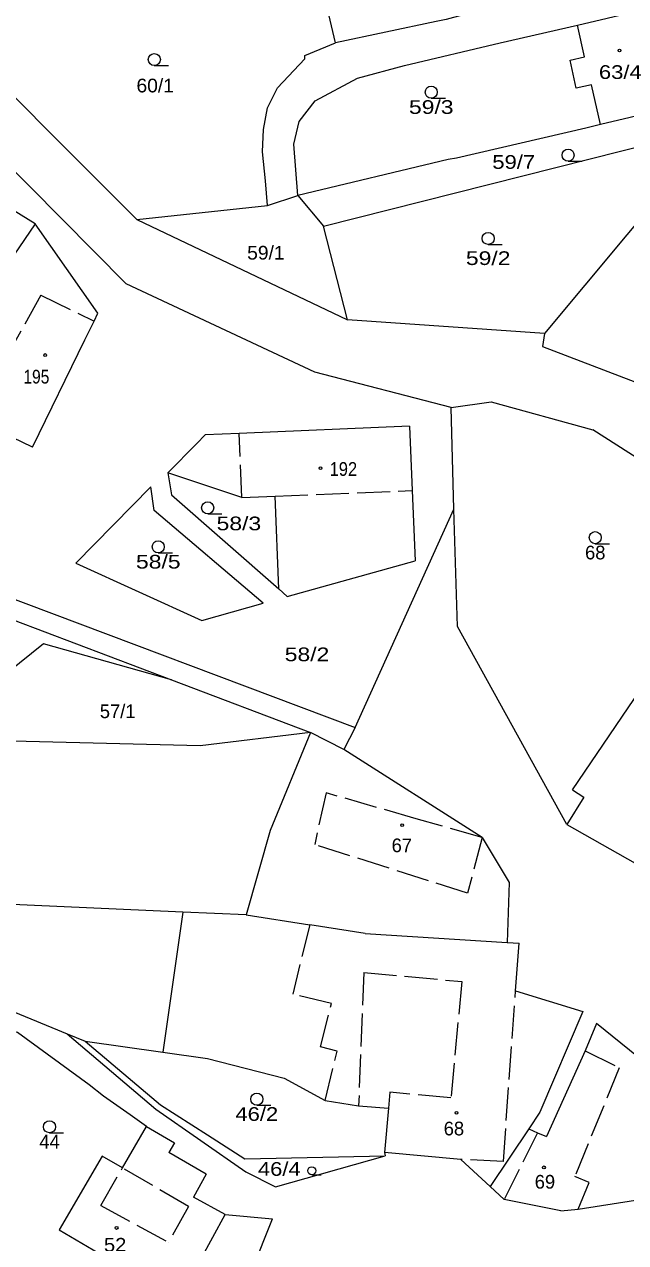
# Model space of a CAD drawing. Extents: x -590528 to -586543, y -1119609 to -1116685.
# Drawn here: x -589235.8 to -589161.2, y -1118589.8 to -1118438.6 of the extents above; entities that cross this region are included whole.
import ezdxf
from ezdxf.enums import TextEntityAlignment as Align

# ---------------------------------------------------------------- set-up
doc = ezdxf.new("R2010")
doc.units = 0
doc.header["$LTSCALE"] = 0.68
doc.linetypes.add('LONG_DASHED', pattern=[7.5, 6, -1.5])
for name, color, linetype, lineweight in [('1', 7, 'Continuous', 13), ('2', 7, 'LONG_DASHED', 13), ('3', 7, 'Continuous', 13), ('6', 7, 'Continuous', 13)]:
    doc.layers.add(name, color=color, linetype=linetype, lineweight=lineweight)

msp = doc.modelspace()

# ---------------------------------------------------------------- linework, layer by layer
at = {"layer": '1'}
for p, q in [((-589197.19, -1118440.86), (-589200.94, -1118424.78)), ((-589223.13, -1118470.78), (-589251.89, -1118441.81)), ((-589234.42, -1118463.35), (-589248.96, -1118454.42)), ((-589205.62, -1118461.09), (-589201.83, -1118459.82)), ((-589201.83, -1118459.82), (-589198.65, -1118463.65)), ((-589234.42, -1118463.35), (-589248.67, -1118484.2)), ((-589226.64, -1118474.44), (-589234.42, -1118463.35)), ((-589221.83, -1118462.82), (-589195.69, -1118475.28)), ((-589199.76, -1118481.77), (-589223.13, -1118470.78)), ((-589227.12, -1118475.43), (-589226.64, -1118474.44)), ((-589182.84, -1118486.15), (-589199.76, -1118481.77)), ((-589182.84, -1118486.15), (-589177.88, -1118485.44)), ((-589177.88, -1118485.44), (-589165.25, -1118488.91)), ((-589209.13, -1118489.36), (-589213.35, -1118489.54)), ((-589188, -1118488.46), (-589209.13, -1118489.36)), ((-589132.93, -1118509.71), (-589165.25, -1118488.91)), ((-589217.98, -1118494.24), (-589217.52, -1118497)), ((-589208.78, -1118497.33), (-589217.98, -1118494.24)), ((-589217.52, -1118497), (-589204.19, -1118508.66)), ((-589208.78, -1118497.33), (-589204.68, -1118497.16)), ((-589204.19, -1118508.66), (-589204.68, -1118497.16)), ((-589206.13, -1118510.45), (-589219.65, -1118498.92)), ((-589194.73, -1118525.89), (-589182.48, -1118498.78)), ((-589203.17, -1118509.62), (-589187.29, -1118505.17)), ((-589246.17, -1118506.49), (-589194.73, -1118525.89)), ((-589203.17, -1118509.62), (-589204.19, -1118508.66)), ((-589168.47, -1118537.9), (-589182.06, -1118513.33)), ((-589167.8, -1118533.6), (-589155.06, -1118514.8)), ((-589217.51, -1118519.97), (-589200.26, -1118526.5)), ((-589194.73, -1118525.89), (-589196.14, -1118528.59)), ((-589179, -1118539.52), (-589196.14, -1118528.59)), ((-589166.37, -1118534.51), (-589168.47, -1118537.9)), ((-589167.8, -1118533.6), (-589166.37, -1118534.51)), ((-589168.47, -1118537.9), (-589152.41, -1118547.01)), ((-589179, -1118539.52), (-589175.63, -1118545.12)), ((-589175.63, -1118545.12), (-589175.87, -1118552.54)), ((-589216.13, -1118548.79), (-589273.08, -1118546.25)), ((-589216.13, -1118548.79), (-589218.59, -1118566.18)), ((-589208.24, -1118549.12), (-589216.13, -1118548.79)), ((-589208.24, -1118549.12), (-589200.37, -1118550.35)), ((-589193.5, -1118551.43), (-589200.37, -1118550.35)), ((-589193.5, -1118551.43), (-589175.87, -1118552.54)), ((-589175.87, -1118552.54), (-589174.41, -1118552.63)), ((-589174.84, -1118558.56), (-589174.41, -1118552.63)), ((-589174.84, -1118558.56), (-589166.5, -1118561.12)), ((-589166.5, -1118561.12), (-589171.84, -1118573.64)), ((-589230.48, -1118563.88), (-589219.46, -1118573.25)), ((-589166.2, -1118566), (-589171.02, -1118576.66)), ((-589198.47, -1118572.17), (-589194.31, -1118572.85)), ((-589194.31, -1118572.85), (-589190.61, -1118573.11)), ((-589190.61, -1118573.11), (-589191.12, -1118578.61)), ((-589223.6, -1118580.55), (-589220.61, -1118575.41)), ((-589220.61, -1118575.41), (-589217.15, -1118577.42)), ((-589217.15, -1118577.42), (-589217.85, -1118578.62)), ((-589226.11, -1118579.09), (-589231.46, -1118588.24)), ((-589223.6, -1118580.55), (-589226.11, -1118579.09)), ((-589213.24, -1118581.3), (-589217.85, -1118578.62)), ((-589178, -1118582.85), (-589181.63, -1118579.49)), ((-589213.24, -1118581.3), (-589214.81, -1118584.18)), ((-589178, -1118582.85), (-589176.27, -1118584.45)), ((-589210.86, -1118586.33), (-589214.81, -1118584.18)), ((-589169.24, -1118585.88), (-589176.27, -1118584.45)), ((-589213.92, -1118591.95), (-589210.86, -1118586.33)), ((-589210.86, -1118586.33), (-589205, -1118586.86)), ((-589208.81, -1118596.45), (-589205, -1118586.86)), ((-589231.46, -1118588.24), (-589219.54, -1118595.2))]:
    msp.add_line(p, q, dxfattribs=at)
for points in [[(-589180.39, -1118419.11), (-589176.44, -1118428.18), (-589175.45, -1118430.45), (-589180.19, -1118432.28), (-589178.39, -1118436.62), (-589183.44, -1118437.97), (-589184.7, -1118438.23), (-589197.19, -1118440.86)], [(-589199.68, -1118448.07), (-589194.46, -1118445.28), (-589188.61, -1118443.7), (-589176.77, -1118440.88), (-589167.18, -1118438.67), (-589159.81, -1118436.94), (-589154.47, -1118435.78), (-589147.85, -1118434.23), (-589145.26, -1118446.55), (-589151.66, -1118448.03), (-589156.96, -1118449.29), (-589164.32, -1118451), (-589166.12, -1118451.49)], [(-589247.08, -1118437.51), (-589221.83, -1118462.82), (-589205.62, -1118461.09)], [(-589164.32, -1118451), (-589165.42, -1118446.1), (-589167.34, -1118446.51), (-589168.07, -1118443.03), (-589166.29, -1118442.63), (-589167.18, -1118438.67)], [(-589205.62, -1118461.09), (-589205.86, -1118458.03), (-589206.24, -1118454.4), (-589206.09, -1118451.65), (-589205.62, -1118448.94), (-589204.36, -1118446.46), (-589201, -1118442.87), (-589200.99, -1118442.47), (-589197.19, -1118440.86)], [(-589201.83, -1118459.82), (-589202.35, -1118453.47), (-589201.69, -1118450.65), (-589199.68, -1118448.07)], [(-589166.12, -1118451.49), (-589182.17, -1118455.21), (-589183.22, -1118455.38), (-589201.83, -1118459.82)], [(-589198.65, -1118463.65), (-589157.55, -1118453.25), (-589156.26, -1118452.88), (-589150.64, -1118451.54), (-589149.64, -1118453.61), (-589148.53, -1118453.2), (-589147.22, -1118453.38), (-589142.56, -1118452.06), (-589142.33, -1118452.99)], [(-589156.03, -1118458.71), (-589171.27, -1118476.97), (-589171.51, -1118478.56)], [(-589171.27, -1118476.97), (-589195.69, -1118475.28), (-589198.65, -1118463.65)], [(-589234.74, -1118491.09), (-589228.25, -1118477.75), (-589227.12, -1118475.43)], [(-589171.51, -1118478.56), (-589144.92, -1118488.74), (-589144.56, -1118485.98)], [(-589234.74, -1118491.09), (-589242.18, -1118487.51), (-589248.67, -1118484.2)], [(-589182.06, -1118513.33), (-589182.48, -1118498.78), (-589182.84, -1118486.15)], [(-589188, -1118488.46), (-589187.66, -1118496.44), (-589187.29, -1118505.17)], [(-589213.35, -1118489.54), (-589214.39, -1118490.6), (-589217.98, -1118494.24)], [(-589219.65, -1118498.92), (-589220.07, -1118496.01), (-589229.39, -1118505.45)], [(-589229.39, -1118505.45), (-589213.76, -1118512.59), (-589206.13, -1118510.45)], [(-589241.14, -1118511.02), (-589217.51, -1118519.97), (-589233.4, -1118515.49), (-589240.89, -1118521.5), (-589277.12, -1118521.87)], [(-589196.14, -1118528.59), (-589200.26, -1118526.5), (-589213.96, -1118528.14), (-589277.11, -1118526.56)], [(-589200.26, -1118526.5), (-589205.27, -1118538.65), (-589208.24, -1118549.12)], [(-589237.59, -1118560.95), (-589230.48, -1118563.88), (-589228.21, -1118564.82)], [(-589220.61, -1118575.41), (-589222.63, -1118573.97), (-589225.96, -1118571.65), (-589227.74, -1118570.24), (-589236.64, -1118563.74), (-589240.88, -1118562.79)], [(-589158.76, -1118567.49), (-589164.81, -1118562.6), (-589166.2, -1118566)], [(-589228.21, -1118564.82), (-589218.9, -1118572.7), (-589213.07, -1118576.42), (-589208.44, -1118579.4), (-589191.01, -1118579.06)], [(-589228.21, -1118564.82), (-589218.59, -1118566.18), (-589213.05, -1118566.97)], [(-589213.05, -1118566.97), (-589203.56, -1118569.39), (-589198.47, -1118572.17)], [(-589169.24, -1118585.88), (-589167.08, -1118585.66), (-589159.98, -1118584.55), (-589143.49, -1118576.26), (-589158.76, -1118567.49)], [(-589219.46, -1118573.25), (-589208.32, -1118581.04), (-589204.63, -1118582.88), (-589191.01, -1118579.06)], [(-589171.84, -1118573.64), (-589173.2, -1118575.68), (-589178, -1118582.85)], [(-589173.2, -1118575.68), (-589172.11, -1118576.17), (-589171.02, -1118576.66)], [(-589181.63, -1118579.49), (-589191.12, -1118578.61), (-589191.01, -1118579.06)]]:
    msp.add_lwpolyline(points, dxfattribs=at)
at = {"layer": '2'}
for p, q in [((-589233.74, -1118472.21), (-589242.18, -1118487.51)), ((-589233.74, -1118472.21), (-589227.12, -1118475.43)), ((-589208.78, -1118497.33), (-589209.13, -1118489.36)), ((-589204.68, -1118497.16), (-589187.66, -1118496.44)), ((-589200.37, -1118550.35), (-589202.49, -1118558.97)), ((-589193.68, -1118556.28), (-589194.31, -1118572.85)), ((-589193.68, -1118556.28), (-589181.52, -1118557.4)), ((-589176.36, -1118579.73), (-589174.84, -1118558.56)), ((-589197.69, -1118560.15), (-589202.49, -1118558.97)), ((-589199.02, -1118565.52), (-589197.69, -1118560.15)), ((-589196.96, -1118566.03), (-589199.02, -1118565.52)), ((-589198.47, -1118572.17), (-589196.96, -1118566.03)), ((-589166.2, -1118566), (-589161.98, -1118568.1)), ((-589161.98, -1118568.1), (-589167.49, -1118581.6)), ((-589172.11, -1118576.17), (-589176.27, -1118584.45)), ((-589176.36, -1118579.73), (-589181.63, -1118579.49)), ((-589226.3, -1118585.19), (-589223.6, -1118580.55)), ((-589215.43, -1118585.31), (-589223.6, -1118580.55)), ((-589165.72, -1118582.33), (-589167.49, -1118581.6)), ((-589167.08, -1118585.66), (-589165.72, -1118582.33)), ((-589226.3, -1118585.19), (-589217.87, -1118589.79)), ((-589215.43, -1118585.31), (-589217.87, -1118589.79))]:
    msp.add_line(p, q, dxfattribs=at)
for points in [[(-589179, -1118539.52), (-589187.17, -1118537.19), (-589198.35, -1118533.98), (-589199.76, -1118540.4)], [(-589179, -1118539.52), (-589180.8, -1118546.43), (-589199.76, -1118540.4)], [(-589181.52, -1118557.4), (-589182.86, -1118571.84), (-589190.43, -1118571.14), (-589190.61, -1118573.11)]]:
    msp.add_lwpolyline(points, dxfattribs=at)
at = {"layer": '6'}
for p, q in [((-589219.65, -1118443.71), (-589217.9, -1118443.71)), ((-589185.3, -1118447.75), (-589183.55, -1118447.75)), ((-589168.33, -1118455.57), (-589166.58, -1118455.57)), ((-589178.24, -1118465.91), (-589176.49, -1118465.91)), ((-589213.03, -1118499.35), (-589211.28, -1118499.35)), ((-589219.16, -1118504.19), (-589217.41, -1118504.19)), ((-589164.96, -1118503.05), (-589163.21, -1118503.05)), ((-589206.94, -1118572.75), (-589205.19, -1118572.75)), ((-589232.65, -1118576.18), (-589230.9, -1118576.18)), ((-589200.12, -1118581.392), (-589198.948, -1118581.392))]:
    msp.add_line(p, q, dxfattribs=at)
for centre, radius in [((-589219.65, -1118442.96), 0.75), ((-589161.9602, -1118441.8404), 0.175), ((-589185.3, -1118447), 0.75), ((-589168.33, -1118454.82), 0.75), ((-589178.24, -1118465.16), 0.75), ((-589233.2002, -1118479.6304), 0.175), ((-589199.0402, -1118493.6704), 0.175), ((-589213.03, -1118498.6), 0.75), ((-589219.16, -1118503.44), 0.75), ((-589164.96, -1118502.3), 0.75), ((-589188.9102, -1118537.9904), 0.175), ((-589206.94, -1118572), 0.75), ((-589182.1702, -1118573.7104), 0.175), ((-589232.65, -1118575.43), 0.75), ((-589200.12, -1118580.89), 0.5025), ((-589171.3202, -1118580.4704), 0.175), ((-589224.3302, -1118587.9904), 0.175)]:
    msp.add_circle(centre, radius, dxfattribs=at)

# ---------------------------------------------------------------- texts
at = {"layer": '3'}
for s, width, p in [('63/4', 1.2, (-589161.8505, -1118445.36)), ('60/1', 1.05, (-589219.5405, -1118447.03)), ('59/3', 1.25, (-589185.3005, -1118449.7)), ('59/7', 1.2, (-589175.0705, -1118456.52)), ('59/1', 1.05, (-589205.8105, -1118467.78)), ('59/2', 1.25, (-589178.24, -1118468.46)), ('195', 0.85, (-589234.2805, -1118483.17)), ('192', 0.9, (-589196.2005, -1118494.63)), ('58/3', 1.25, (-589209.1605, -1118501.39)), ('58/5', 1.25, (-589219.16, -1118506.14)), ('58/2', 1.25, (-589200.71, -1118517.64)), ('46/2', 1.2, (-589206.94, -1118574.7)), ('46/4', 1.2, (-589204.1505, -1118581.52)), ('52', 1.1, (-589224.51, -1118590.93))]:
    msp.add_text(s, height=1.7, dxfattribs=dict(at, width=width)).set_placement(p, align=Align.CENTER)
for s, p in [('68', (-589164.96, -1118505)), ('57/1', (-589224.2005, -1118524.71)), ('67', (-589188.9505, -1118541.35)), ('68', (-589182.49, -1118576.5)), ('44', (-589232.6505, -1118578.13)), ('69', (-589171.2005, -1118583.11))]:
    msp.add_text(s, height=1.7, dxfattribs=at).set_placement(p, align=Align.CENTER)

doc.saveas('drawing.dxf')
